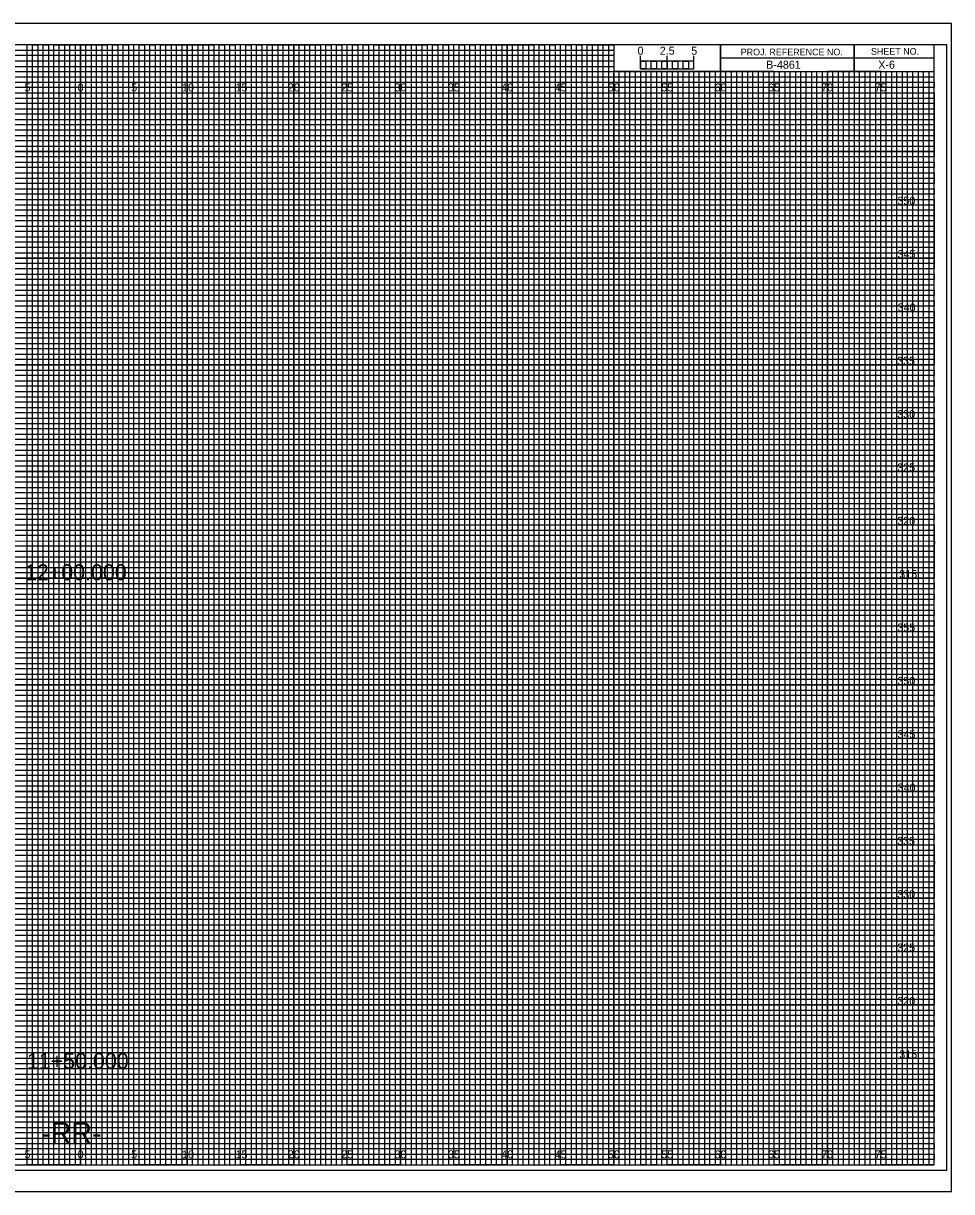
# Model space of a CAD drawing. Extents: x -7 to 162, y -2 to 327.
# Drawn here: x 74.6 to 161.7, y 107.5 to 217 of the extents above; entities that cross this region are included whole.
import ezdxf

# ---------------------------------------------------------------- set-up
doc = ezdxf.new("R2010")
doc.units = 0
for name, color, linetype in [('Exist Cross Section Cell', 7, 'Continuous'), ('Exist XS Center Line Elevation Label', 7, 'Continuous'), ('Exist XS Ground Line', 7, 'Continuous'), ('Old_Level_1', 7, 'Continuous'), ('Prop Retaining Wall', 7, 'Continuous'), ('Prop XS Bar Scale Labels', 7, 'Continuous'), ('Prop XS Bridge', 7, 'Continuous'), ('Prop XS Ditch Standard Text', 7, 'Continuous'), ('Prop XS EOT Tick Mark', 7, 'Continuous'), ('Prop XS Finish Grade Concrete', 7, 'Continuous'), ('Prop XS Finish Grade Earthwork', 7, 'Continuous'), ('Prop XS Label Text', 7, 'Continuous'), ('Prop XS SS Elevation Text', 7, 'Continuous'), ('Prop XS Subgrade', 7, 'Continuous'), ('Scratch_Level_3', 7, 'Continuous'), ('Scratch_Level_4', 7, 'Continuous'), ('Typical Arrow Superelevation CELL', 7, 'Continuous')]:
    doc.layers.add(name, color=color, linetype=linetype)

msp = doc.modelspace()

# ---------------------------------------------------------------- linework, layer by layer
at = {"layer": 'Exist XS Center Line Elevation Label'}
for points in [[(72.5, 110), (77.5, 110), (77.5, 215), (82.5, 215), (82.5, 110), (87.5, 110), (87.5, 215), (92.5, 215), (92.5, 110), (97.5, 110), (97.5, 215), (102.5, 215), (102.5, 110), (107.5, 110), (107.5, 215), (112.5, 215), (112.5, 110), (117.5, 110), (117.5, 215), (122.5, 215), (122.5, 110), (127.5, 110), (127.5, 215), (129.97, 215), (130, 215), (130, 212.5), (132.5, 212.5), (132.5, 110), (137.5, 110), (137.5, 212.5), (142.5, 212.5), (142.5, 110), (147.5, 110), (147.5, 212.5), (152.5, 212.5), (152.5, 110), (157.5, 110), (157.5, 212.5)], [(0, 212.5), (137.5, 212.5)], [(0, 202.5), (160, 202.5), (160, 207.5), (0, 207.5)], [(0, 192.5), (160, 192.5), (160, 197.5), (0, 197.5)], [(0, 182.5), (160, 182.5), (160, 187.5), (0, 187.5)], [(0, 172.5), (160, 172.5), (160, 177.5), (0, 177.5)], [(0, 162.5), (160, 162.5), (160, 167.5), (0, 167.5)], [(0, 152.5), (160, 152.5), (160, 157.5), (0, 157.5)], [(0, 142.5), (160, 142.5), (160, 147.5), (0, 147.5)], [(0, 132.5), (160, 132.5), (160, 137.5), (0, 137.5)], [(0, 122.5), (160, 122.5), (160, 127.5), (0, 127.5)], [(0, 112.5), (160, 112.5), (160, 117.5), (0, 117.5)]]:
    msp.add_lwpolyline(points, dxfattribs=at)
at = {"layer": 'Exist XS Ground Line'}
for p, q in [((75, 215), (70, 215)), ((75, 110), (75, 215)), ((85, 215), (80, 215)), ((80, 215), (80, 110)), ((85, 110), (85, 215)), ((95, 215), (90, 215)), ((90, 215), (90, 110)), ((95, 110), (95, 215)), ((105, 215), (100, 215)), ((100, 215), (100, 110)), ((105, 110), (105, 215)), ((115, 215), (110, 215)), ((110, 215), (110, 110)), ((115, 110), (115, 215)), ((125, 215), (120, 215)), ((120, 215), (120, 110)), ((125, 110), (125, 215)), ((130, 215), (130, 110)), ((135, 110), (135, 212.5)), ((145, 212.5), (140, 212.5)), ((140, 212.5), (140, 110)), ((145, 110), (145, 212.5)), ((155, 212.5), (150, 212.5)), ((150, 212.5), (150, 110)), ((155, 110), (155, 212.5)), ((80, 110), (75, 110)), ((90, 110), (85, 110)), ((100, 110), (95, 110)), ((110, 110), (105, 110)), ((120, 110), (115, 110)), ((130, 110), (125, 110)), ((140, 110), (135, 110)), ((150, 110), (145, 110)), ((160, 110), (155, 110)), ((160, 110), (160, 110))]:
    msp.add_line(p, q, dxfattribs=at)
for points in [[(0, 210), (160, 210), (160, 205), (0, 205)], [(0, 200), (160, 200), (160, 195), (0, 195)], [(0, 190), (160, 190), (160, 185), (0, 185)], [(0, 180), (160, 180), (160, 175), (0, 175)], [(0, 170), (160, 170), (160, 165), (0, 165)], [(0, 160), (160, 160), (160, 155), (0, 155)], [(0, 150), (160, 150), (160, 145), (0, 145)], [(0, 140), (160, 140), (160, 135), (0, 135)], [(0, 130), (160, 130), (160, 125), (0, 125)], [(0, 120), (160, 120), (160, 115), (0, 115)]]:
    msp.add_lwpolyline(points, dxfattribs=at)
at = {"layer": 'Old_Level_1'}
msp.add_lwpolyline([(-5.4, 109.5), (161.2, 109.5), (161.2, 215), (-5.4, 215)], close=True, dxfattribs=at)
at = {"layer": 'Prop XS Bridge'}
for p, q in [((75, 110), (75, 215)), ((80, 110), (80, 215)), ((85, 110), (85, 215)), ((90, 110), (90, 215)), ((95, 110), (95, 215)), ((100, 110), (100, 215)), ((105, 110), (105, 215)), ((110, 110), (110, 215)), ((115, 110), (115, 215)), ((120, 110), (120, 215)), ((125, 110), (125, 215)), ((130, 110), (130, 212.34)), ((135, 110), (135, 212.34)), ((140, 110), (140, 212.34)), ((145, 110), (145, 212.34)), ((150, 110), (150, 212.34)), ((155, 110), (155, 212.34)), ((0, 210), (160, 210)), ((0, 205), (160, 205)), ((0, 200), (160, 200)), ((0, 195), (160, 195)), ((0, 190), (160, 190)), ((0, 185), (160, 185)), ((0, 180), (160, 180)), ((0, 175), (160, 175)), ((0, 170), (160, 170)), ((0, 165), (160, 165)), ((0, 160), (160, 160)), ((0, 155), (160, 155)), ((0, 150), (160, 150)), ((0, 145), (160, 145)), ((0, 140), (160, 140)), ((0, 135), (160, 135)), ((0, 130), (160, 130)), ((0, 125), (160, 125)), ((0, 120), (160, 120)), ((0, 115), (160, 115))]:
    msp.add_line(p, q, dxfattribs=at)
at = {"layer": 'Prop XS EOT Tick Mark'}
for p, q in [((152.5, 215), (152.5, 212.5)), ((152.5, 212.5), (152.5, 215)), ((160, 213.75), (140, 213.75)), ((140, 213.75), (140, 212.5)), ((140, 212.5), (160, 212.5))]:
    msp.add_line(p, q, dxfattribs=at)
for points in [[(160, 215), (0, 215), (0, 110), (160, 110)], [(140, 215), (130, 215), (130, 212.52), (140, 212.52)], [(160, 215), (140, 215), (140, 212.5), (160, 212.5)]]:
    msp.add_lwpolyline(points, close=True, dxfattribs=at)
at = {"layer": 'Prop XS Finish Grade Earthwork'}
for p, q in [((161.65, 217), (-6.7, 217)), ((-6.7, 107.5), (161.65, 107.5))]:
    msp.add_line(p, q, dxfattribs=at)
at = {"layer": 'Prop XS Label Text'}
for p, q in [((133.5, 212.5), (133, 212.5)), ((133, 212.5), (133, 110)), ((133.5, 110), (133.5, 212.5)), ((134.5, 212.5), (134, 212.5)), ((134, 212.5), (134, 110)), ((134.5, 110), (134.5, 212.5)), ((133, 110), (132.5, 110)), ((134, 110), (133.5, 110))]:
    msp.add_line(p, q, dxfattribs=at)
for points in [[(75, 110), (75.5, 110), (75.5, 215), (76, 215), (76, 110)], [(76, 110), (76.5, 110), (76.5, 215), (77, 215), (77, 110)], [(77.5, 110), (78, 110), (78, 215), (78.5, 215), (78.5, 110)], [(78.5, 110), (79, 110), (79, 215), (79.5, 215), (79.5, 110)], [(80, 110), (80.5, 110), (80.5, 215), (81, 215), (81, 110)], [(81, 110), (81.5, 110), (81.5, 215), (82, 215), (82, 110)], [(82.5, 110), (83, 110), (83, 215), (83.5, 215), (83.5, 110)], [(83.5, 110), (84, 110), (84, 215), (84.5, 215), (84.5, 110)], [(85, 110), (85.5, 110), (85.5, 215), (86, 215), (86, 110)], [(86, 110), (86.5, 110), (86.5, 215), (87, 215), (87, 110)], [(87.5, 110), (88, 110), (88, 215), (88.5, 215), (88.5, 110)], [(88.5, 110), (89, 110), (89, 215), (89.5, 215), (89.5, 110)], [(90, 110), (90.5, 110), (90.5, 215), (91, 215), (91, 110)], [(91, 110), (91.5, 110), (91.5, 215), (92, 215), (92, 110)], [(92.5, 110), (93, 110), (93, 215), (93.5, 215), (93.5, 110)], [(93.5, 110), (94, 110), (94, 215), (94.5, 215), (94.5, 110)], [(95, 110), (95.5, 110), (95.5, 215), (96, 215), (96, 110)], [(96, 110), (96.5, 110), (96.5, 215), (97, 215), (97, 110)], [(97.5, 110), (98, 110), (98, 215), (98.5, 215), (98.5, 110)], [(98.5, 110), (99, 110), (99, 215), (99.5, 215), (99.5, 110)], [(100, 110), (100.5, 110), (100.5, 215), (101, 215), (101, 110)], [(101, 110), (101.5, 110), (101.5, 215), (102, 215), (102, 110)], [(102.5, 110), (103, 110), (103, 215), (103.5, 215), (103.5, 110)], [(103.5, 110), (104, 110), (104, 215), (104.5, 215), (104.5, 110)], [(105, 110), (105.5, 110), (105.5, 215), (106, 215), (106, 110)], [(106, 110), (106.5, 110), (106.5, 215), (107, 215), (107, 110)], [(107.5, 110), (108, 110), (108, 215), (108.5, 215), (108.5, 110)], [(108.5, 110), (109, 110), (109, 215), (109.5, 215), (109.5, 110)], [(110, 110), (110.5, 110), (110.5, 215), (111, 215), (111, 110)], [(111, 110), (111.5, 110), (111.5, 215), (112, 215), (112, 110)], [(112.5, 110), (113, 110), (113, 215), (113.5, 215), (113.5, 110)], [(113.5, 110), (114, 110), (114, 215), (114.5, 215), (114.5, 110)], [(115, 110), (115.5, 110), (115.5, 215), (116, 215), (116, 110)], [(116, 110), (116.5, 110), (116.5, 215), (117, 215), (117, 110)], [(117.5, 110), (118, 110), (118, 215), (118.5, 215), (118.5, 110)], [(118.5, 110), (119, 110), (119, 215), (119.5, 215), (119.5, 110)], [(120, 110), (120.5, 110), (120.5, 215), (121, 215), (121, 110)], [(121, 110), (121.5, 110), (121.5, 215), (122, 215), (122, 110)], [(122.5, 110), (123, 110), (123, 215), (123.5, 215), (123.5, 110)], [(123.5, 110), (124, 110), (124, 215), (124.5, 215), (124.5, 110)], [(125, 110), (125.5, 110), (125.5, 215), (126, 215), (126, 110)], [(126, 110), (126.5, 110), (126.5, 215), (127, 215), (127, 110)], [(127.5, 110), (128, 110), (128, 215), (128.5, 215), (128.5, 110)], [(128.5, 110), (129, 110), (129, 215), (129.5, 215), (129.5, 110)], [(130, 110), (130.5, 110), (130.5, 212.5), (131.01, 212.5), (131.01, 110)], [(131, 110), (131.5, 110), (131.5, 212.5), (132, 212.5), (132, 110)], [(135, 110), (135.49, 110), (135.49, 212.5), (136, 212.5), (136, 110)], [(136, 110), (136.5, 110), (136.5, 212.5), (137.03, 212.5), (137.03, 110)], [(137.5, 110), (138, 110), (138, 212.5), (138.5, 212.5), (138.5, 110)], [(138.5, 110), (139, 110), (139, 212.5), (139.5, 212.5), (139.5, 110)], [(140, 110), (140.5, 110), (140.5, 212.5), (141, 212.5), (141, 110)], [(141, 110), (141.5, 110), (141.5, 212.5), (142, 212.5), (142, 110)], [(142.5, 110), (143, 110), (143, 212.5), (143.5, 212.5), (143.5, 110)], [(143.5, 110), (144, 110), (144, 212.5), (144.5, 212.5), (144.5, 110)], [(145, 110), (145.5, 110), (145.5, 212.5), (146, 212.5), (146, 110)], [(146, 110), (146.5, 110), (146.5, 212.5), (147, 212.5), (147, 110)], [(147.5, 110), (148, 110), (148, 212.5), (148.5, 212.5), (148.5, 110)], [(148.5, 110), (149, 110), (149, 212.5), (149.5, 212.5), (149.5, 110)], [(150, 110), (150.5, 110), (150.5, 212.5), (151, 212.5), (151, 110)], [(151, 110), (151.5, 110), (151.5, 212.5), (152, 212.5), (152, 110)], [(152.5, 110), (153, 110), (153, 212.5), (153.5, 212.5), (153.5, 110)], [(153.5, 110), (154, 110), (154, 212.5), (154.5, 212.5), (154.5, 110)], [(155, 110), (155.5, 110), (155.5, 212.5), (156, 212.5), (156, 110)], [(156, 110), (156.5, 110), (156.5, 212.5), (157, 212.5), (157, 110)], [(157.5, 110), (158, 110), (158, 212.5), (158.5, 212.5), (158.5, 110)], [(158.5, 110), (159, 110), (159, 212.5), (159.5, 212.5), (159.5, 110)]]:
    msp.add_lwpolyline(points, dxfattribs=at)
at = {"layer": 'Prop XS Subgrade'}
msp.add_lwpolyline([(-6.7, 107.5), (161.65, 107.5), (161.65, 217), (-6.7, 217)], close=True, dxfattribs=at)
at = {"layer": 'Scratch_Level_3'}
for p, q in [((0, 214.5), (130, 214.5)), ((130, 213.99), (0, 213.99)), ((130, 214.5), (130, 213.99)), ((0, 213.5), (130, 213.5)), ((130, 212.94), (0, 212.94)), ((130, 213.5), (130, 212.94)), ((0, 212), (160, 212))]:
    msp.add_line(p, q, dxfattribs=at)
for points in [[(0, 211.5), (135, 211.5), (160, 211.5), (160, 211), (0, 211)], [(0, 210.5), (160, 210.5), (160, 209.5), (0, 209.5)], [(0, 209), (160, 209), (160, 208.5), (0, 208.49)], [(0, 208), (160, 208), (160, 207), (0, 207)], [(0, 206.5), (160, 206.5), (160, 206), (0, 206)], [(0, 205.5), (160, 205.5), (160, 204.5), (0, 204.5)], [(0, 204), (160, 204), (160, 203.5), (0, 203.5)], [(0, 203), (160, 203), (160, 202), (0, 202)], [(0, 201.5), (160, 201.5), (160, 201), (0, 201)], [(0, 200.5), (160, 200.5), (160, 199.5), (0, 199.5)], [(0, 199), (160, 199), (160, 198.5), (0, 198.5)], [(0, 198), (160, 198), (160, 196.97), (160, 196.5), (160, 196), (0, 196)], [(0, 197), (160, 197), (160, 196.5), (0, 196.5)], [(0, 195.5), (160, 195.5), (160, 194.5), (0, 194.52)], [(0, 194.52), (160, 194.5), (160, 194), (0, 194)], [(0, 193.5), (160, 193.5), (160, 193), (0, 193)], [(0, 192), (160, 192), (160, 191.5), (0, 191.5)], [(0, 191), (160, 191), (160, 190.5), (0, 190.5)], [(-0.04, 189.44), (160, 189.44), (160, 188.94), (-0.04, 188.94)], [(0, 188.5), (160, 188.5), (160, 188), (0, 188)], [(0, 187), (160, 187), (160, 186.5), (0, 186.5)], [(0, 186), (160, 186), (160, 185.5), (0, 185.5)], [(0, 184.5), (160, 184.5), (160, 184), (0, 184)], [(0, 183.5), (160, 183.5), (160, 183), (0, 183)], [(0, 182), (160, 182), (160, 181.5), (0, 181.5)], [(0, 181), (160, 181), (160, 180.5), (0, 180.5)], [(0, 179.5), (160, 179.5), (160, 178.99), (0, 179)], [(0, 178.5), (160, 178.5), (160, 178), (0, 178)], [(0, 177), (160, 177), (160, 176.5), (0, 176.5)], [(0, 176), (160, 176), (160, 175.5), (0, 175.5)], [(0, 174.5), (160, 174.5), (160, 174), (0, 174)], [(0, 173.5), (160, 173.5), (160, 173), (0, 173)], [(0, 172), (160, 172), (160, 171.5), (0, 171.5)], [(0, 171), (160, 171), (160, 170.5), (0, 170.5)], [(0, 169.5), (160, 169.5), (160, 169), (0, 169)], [(0, 168.5), (160.03, 168.46), (160, 168), (0, 168)], [(0, 167), (160, 167), (160, 166.5), (0, 166.5)], [(0, 166), (160, 166), (160, 165.5), (0, 165.5)], [(0, 164.5), (160, 164.5), (160, 164), (0, 164)], [(0, 163.5), (160, 163.5), (160, 163), (0, 163)], [(0, 162), (160, 162), (160, 161.5), (0, 161.5)], [(0, 161), (160, 161), (160, 160.5), (0, 160.5)], [(0, 159.5), (160, 159.5), (160, 159), (0, 159)], [(0, 158.5), (160, 158.5), (160, 158), (0, 158)], [(0, 157), (160, 157), (160, 156.5), (0, 156.5)], [(0, 156), (160, 156), (160, 155.5), (0, 155.5)], [(0, 154.5), (160, 154.5), (160, 154), (0, 154)], [(0, 153.5), (160, 153.5), (160, 153), (0, 153)], [(0, 152), (160, 152), (160, 151.5), (0, 151.5)], [(0, 151), (160, 151), (160, 150.5), (0, 150.5)], [(0, 149.5), (160, 149.5), (160, 148.99), (0, 149)], [(0, 148.5), (160, 148.5), (160, 148), (0, 148)], [(0, 147), (160, 147), (160, 146.5), (0, 146.5)], [(0, 146), (160, 146), (160, 145.5), (0, 145.5)], [(0, 144.5), (160, 144.5), (160, 144), (0, 144)], [(0, 143.5), (160, 143.5), (160, 143), (0, 143)], [(0, 142), (160, 142), (160, 141.5), (0, 141.5)], [(0, 141), (160, 141), (160, 140.5), (0, 140.5)], [(0, 139.5), (160, 139.5), (160, 139), (0, 139)], [(0, 138.5), (160.03, 138.46), (160, 138), (0, 138)], [(0, 137), (160, 137), (160, 136.5), (0, 136.5)], [(0, 136), (160, 136), (160, 135.5), (0, 135.5)], [(0, 134.5), (160, 134.5), (160, 134), (0, 134)], [(0, 133.5), (160, 133.5), (160, 133), (0, 133)], [(0, 132), (160, 132), (160, 131.5), (0, 131.5)], [(0, 131), (160, 131), (160, 130.5), (0, 130.5)], [(0, 129.5), (160, 129.5), (160, 129), (0, 129)], [(0, 128.5), (160, 128.5), (160, 128), (0, 128)], [(0, 127), (160, 127), (160, 126.5), (0, 126.5)], [(0, 126), (160, 126), (160, 125.5), (0, 125.5)], [(0, 124.5), (160, 124.5), (160, 124), (0, 124)], [(0, 123.5), (160, 123.5), (160, 123), (0, 123)], [(0, 122), (160, 122), (160, 121.5), (0, 121.5)], [(0, 121), (160, 121), (160, 120.5), (0, 120.5)], [(0, 119.5), (160, 119.5), (160, 119), (0, 119)], [(0, 118.5), (160, 118.5), (160, 118), (0, 118)], [(0, 117), (160, 117), (160, 116.5), (0, 116.5)], [(0, 116), (160, 116), (160, 115.5), (0, 115.5)], [(0, 114.5), (160, 114.5), (160, 114), (0, 114)], [(0, 113.5), (160, 113.5), (160, 113), (0, 113)], [(0, 112), (160, 112), (160, 111.5), (0, 111.5)], [(0, 111), (160, 111), (160, 110.5), (0, 110.5)]]:
    msp.add_lwpolyline(points, dxfattribs=at)
at = {"layer": 'Scratch_Level_4'}
for p, q in [((132.5, 212.75), (132.5, 213.95)), ((132.5, 213.45), (132.5, 213.95)), ((135, 212.75), (135, 213.95)), ((137.5, 212.75), (137.5, 213.95)), ((137.5, 213.45), (137.5, 213.95))]:
    msp.add_line(p, q, dxfattribs=at)
for points in [[(137.5, 213.45), (132.5, 213.45), (132.5, 212.75), (137.5, 212.75)], [(132.5, 213.45), (133, 213.45), (133, 212.75), (132.5, 212.75)], [(133.5, 213.45), (134, 213.45), (134, 212.75), (133.5, 212.75)], [(134.5, 213.45), (135, 213.45), (135, 212.75), (134.5, 212.75)], [(135.5, 213.45), (136, 213.45), (136, 212.75), (135.5, 212.75)], [(136.5, 213.45), (137, 213.45), (137, 212.75), (136.5, 212.75)]]:
    msp.add_lwpolyline(points, close=True, dxfattribs=at)

# ---------------------------------------------------------------- texts
at = {"layer": 'Exist Cross Section Cell'}
for s, p in [('5', (74.74, 210.62)), ('0', (79.73, 210.62)), ('0', (79.73, 210.62)), ('5', (84.74, 210.62)), ('10', (89.52, 210.62)), ('15', (94.53, 210.62)), ('20', (99.43, 210.62)), ('25', (104.44, 210.62)), ('30', (109.43, 210.62)), ('35', (114.44, 210.62)), ('40', (119.43, 210.62)), ('45', (124.44, 210.62)), ('50', (129.43, 210.62)), ('55', (134.44, 210.62)), ('60', (139.43, 210.62)), ('65', (144.44, 210.62)), ('70', (149.43, 210.62)), ('75', (154.44, 210.62)), ('5', (74.74, 110.62)), ('0', (79.73, 110.62)), ('0', (79.73, 110.62)), ('5', (84.74, 110.62)), ('10', (89.52, 110.62)), ('15', (94.53, 110.62)), ('20', (99.43, 110.62)), ('25', (104.44, 110.62)), ('30', (109.43, 110.62)), ('35', (114.44, 110.62)), ('40', (119.43, 110.62)), ('45', (124.44, 110.62)), ('50', (129.43, 110.62)), ('55', (134.44, 110.62)), ('60', (139.43, 110.62)), ('65', (144.44, 110.62)), ('70', (149.43, 110.62)), ('75', (154.44, 110.62))]:
    msp.add_text(s, height=0.75, dxfattribs=at).set_placement(p)
at = {"layer": 'Prop Retaining Wall'}
msp.add_text('-RR-', height=2, dxfattribs=at).set_placement((76.32, 112))
at = {"layer": 'Prop XS Bar Scale Labels'}
for s, p in [('2.5', (134.29, 214.06)), ('5', (137.24, 214.06))]:
    msp.add_text(s, height=0.75, dxfattribs=at).set_placement(p)
at = {"layer": 'Prop XS Ditch Standard Text'}
for s, p in [('350', (156.57, 200)), ('345', (156.58, 195)), ('340', (156.59, 190)), ('335', (156.54, 185)), ('330', (156.55, 180)), ('325', (156.55, 175)), ('320', (156.56, 170)), ('315', (156.74, 165)), ('355', (156.56, 160)), ('350', (156.57, 155)), ('345', (156.58, 150)), ('340', (156.59, 145)), ('335', (156.54, 140)), ('330', (156.55, 135)), ('325', (156.55, 130)), ('320', (156.56, 125)), ('315', (156.74, 120))]:
    msp.add_text(s, height=0.75, dxfattribs=at).set_placement(p)
at = {"layer": 'Prop XS EOT Tick Mark'}
for s, p in [('PROJ. REFERENCE NO.', (141.88, 214)), ('SHEET NO.', (154.09, 214.06))]:
    msp.add_text(s, height=0.625, dxfattribs=at).set_placement(p)
at = {"layer": 'Prop XS Finish Grade Concrete'}
for s, p in [('12+00.000', (74.79, 164.8)), ('11+50.000', (74.97, 119))]:
    msp.add_text(s, height=1.5, dxfattribs=at).set_placement(p)
at = {"layer": 'Prop XS SS Elevation Text'}
msp.add_text('B-4861', height=0.75, dxfattribs=at).set_placement((144.27, 212.75))
at = {"layer": 'Scratch_Level_4'}
msp.add_text('0', height=0.75, dxfattribs=at).set_placement((132.21, 214.06))
at = {"layer": 'Typical Arrow Superelevation CELL'}
msp.add_text('X-6', height=0.75, dxfattribs=at).set_placement((154.77, 212.75))

doc.saveas('drawing.dxf')
